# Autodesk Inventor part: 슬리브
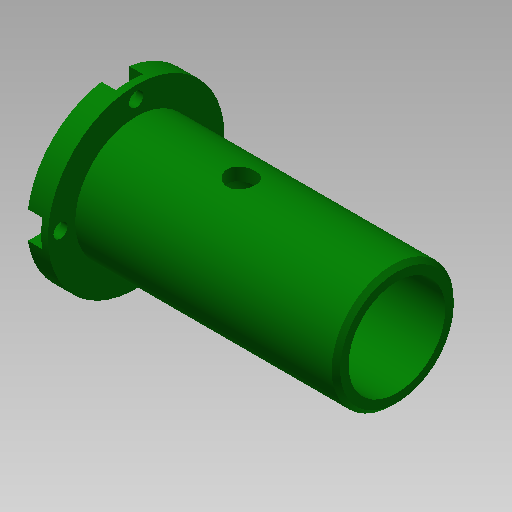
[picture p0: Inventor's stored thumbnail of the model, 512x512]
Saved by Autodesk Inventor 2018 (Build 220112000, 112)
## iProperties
Created: 2019-10
Part Number: 슬리브
Material: 알루미늄 6061
Document SubType Name: Modeling
Designer: mduedu
Density: 1 g/cm^3
Appearance: 진녹색
Author: mduedu
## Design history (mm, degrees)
sketch "스케치1"
  geometry: L1 (0, 0)-(5, 0); L2 (5, 0)-(5, 21); L3 (5, 21)-(0, 21); L4 (0, 21)-(0, 0); L5 (5, 0)-(67, 0); L6 (67, 0)-(67, 14.5); L7 (67, 14.5)-(5, 14.5); L8 (5, 14.5)-(5, 0)
  constraints: 16 end point, 4 parallel, 2 horizontal, 2 perpendicular
  dimensions: "d0" = 67 distance between parallel lines of L6 L4; "d2" = 62 distance of L6.end L7.end; "d3" = 42 diameter of L3 L1; "d4" = 29 diameter of L7 L5
revolve "회전1" sketch "스케치1" stored, may be unused: angle "d5" = 90 deg
hole "구멍1" diameter "d8" = 23; stored, may be unused: countersink angle "d12" = 90 deg, drill point angle "d14" = 118 deg; dims "d6" = 10, "d7" = 10, "d9" = 6, "d10" = 4, "d11" = 2, "d13" = 8
sketch "스케치2"
  geometry: L1 (-5, 21)-(-5, -21) reference; C1 r 3.3 at (-30, 0); 1 further point
  constraints: 1 centre point, 1 horizontal alignment
  dimensions: "d15" = 6.6 diameter of C1; "d16" = 25 distance from line of C1.centre L1
extrude "돌출1" cut sketch "스케치2" extent not by distance; stored distance "d17" = 10; taper "d18" = 0 deg
chamfer "모따기1" distance "d19" = 1; stored, may be unused: second distance "d20" = 2, angle "d21" = 45 deg
sketch "스케치3" dims "d22" = 36
  geometry: 6 further points
  constraints: 2 vertical alignment, 1 coincident, 7 other
  dimensions: "d25" = 360 deg dimension on point (0, 0) point (0, 18) (derived)
sketch "스케치4"
  geometry: 4 further points
  constraints: 4 other
hole "구멍2" sketch "스케치4" at (-18, 0), (0, -18), (18, 0), (0, 18) diameter "d27" = 3.4; stored, may be unused: countersink angle "d31" = 90 deg, drill point angle "d33" = 0 deg; dims "d28" = 6, "d29" = 6.5, "d30" = 3.4, "d32" = 8
sketch "스케치5"
  geometry: L1 (-21.25, 20.747)-(-21.25, 18); L2 (-14.75, 18)-(-14.75, 20.747); A1 r 3.25 centre (-18, 18) between (-19.349, 20.957) and (-16.651, 20.957) reference; A2 r 21 centre (-18, 0) between (-19.349, 20.957) and (-38.957, 1.349) reference; A3 r 21 centre (-18, 0) between (2.957, 1.349) and (-16.651, 20.957) reference; A4 r 21 centre (-18, 0) between (-14.75, 20.747) and (-21.25, 20.747); A5 r 3.25 centre (-18, 18) between (-21.25, 18) and (-14.75, 18); 1 further point
  constraints: 8 point on circle, 4 end point, 2 centre point, 2 coincident, 2 tangent, 1 parallel, 1 vertical
extrude "돌출2" cut sketch "스케치5" stored distance "d34" = 10; taper "d35" = 0 deg
node "솔리드1"
pattern_circular "원형 패턴1" dims angle "d37" = 360 deg
